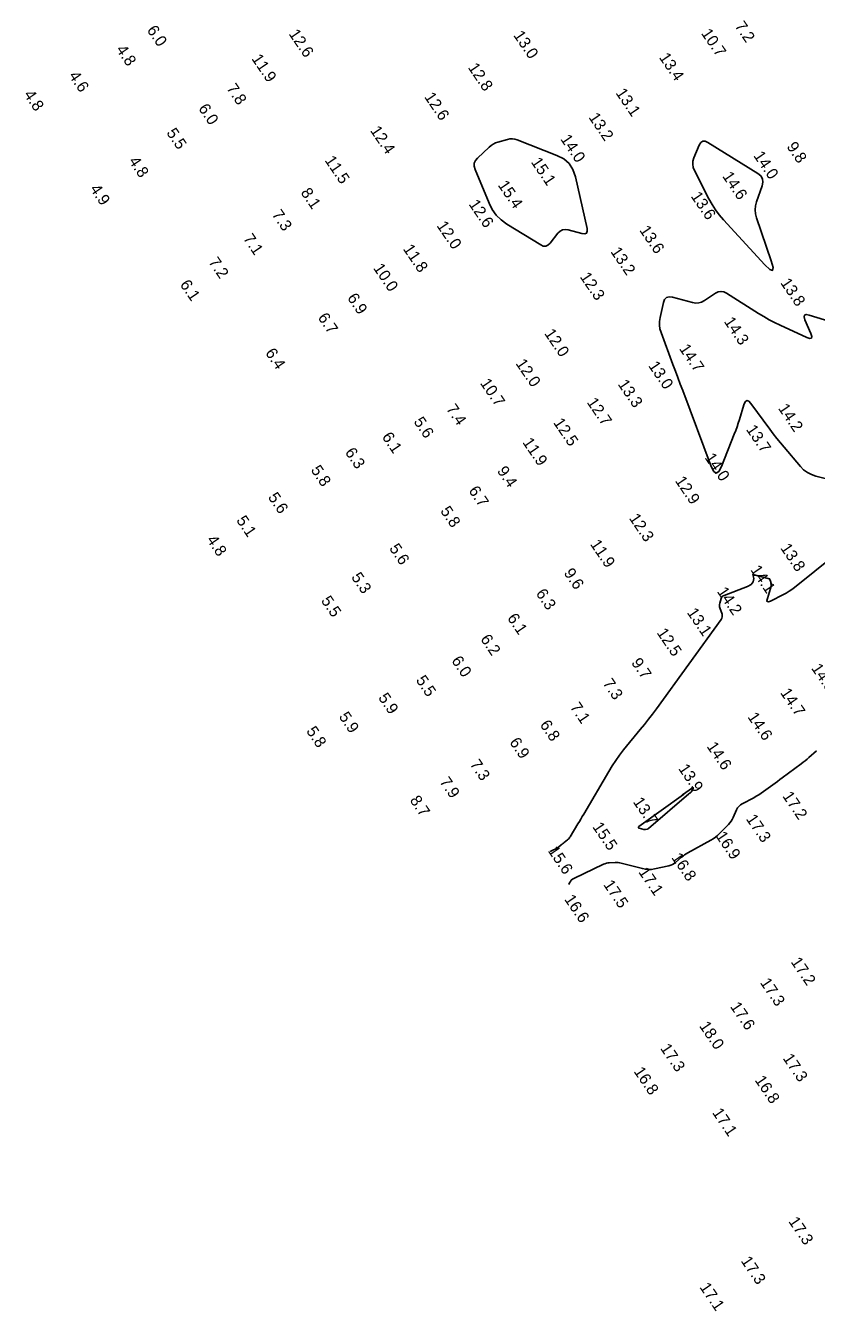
# Model space of a CAD drawing. Extents: x 824616 to 827440, y 158441 to 163197.
# Drawn here: x 826004 to 826349, y 160339 to 160899 of the extents above; entities that cross this region are included whole.
import ezdxf

# ---------------------------------------------------------------- set-up
doc = ezdxf.new("R2010")
doc.units = 0
for name, color, linetype in [('V-CHAN-CONT-EL14', 7, 'Continuous'), ('V-CHAN-CONT-EL16', 7, 'Continuous'), ('V-TOPO-SOUN', 7, 'Continuous')]:
    doc.layers.add(name, color=color, linetype=linetype)

msp = doc.modelspace()

# ---------------------------------------------------------------- linework, layer by layer
at = {"layer": 'V-CHAN-CONT-EL14'}
for points in [[(826199.82, 160838.98), (826199.77, 160837.69), (826200.14, 160836.32), (826206.22, 160821.63), (826207.62, 160818.86), (826209.38, 160816.42), (826211.52, 160814.28), (826214.02, 160812.47), (826228.72, 160803.41), (826229.87, 160802.91), (826230.93, 160802.86), (826231.91, 160803.27), (826232.81, 160804.14), (826236.23, 160808.52), (826237.15, 160809.44), (826238.19, 160809.99), (826239.35, 160810.18), (826240.64, 160810.01), (826246.68, 160808.42), (826247.91, 160808.27), (826248.7, 160808.58), (826249.04, 160809.36), (826248.93, 160810.59), (826243.82, 160833.12), (826242.75, 160836.24), (826241.06, 160838.83), (826238.75, 160840.89), (826235.82, 160842.42), (826218.47, 160849.19), (826217.44, 160849.5), (826216.4, 160849.64), (826215.35, 160849.6), (826214.3, 160849.38), (826210.06, 160848.17), (826209.03, 160847.81), (826208.07, 160847.33), (826207.17, 160846.75), (826206.33, 160846.05), (826201.21, 160841.26), (826200.3, 160840.16)], [(826294.94, 160838.54), (826295.15, 160837.18), (826295.68, 160835.83), (826301.98, 160823.52), (826303.34, 160821.08), (826304.85, 160818.74), (826306.52, 160816.51), (826308.34, 160814.39), (826326.38, 160794.79), (826328.54, 160792.73), (826329.72, 160792.32), (826329.93, 160793.55), (826329.15, 160796.44), (826322.76, 160815.2), (826322.31, 160816.94), (826322.17, 160818.68), (826322.32, 160820.43), (826322.78, 160822.17), (826325.18, 160829.14), (826325.52, 160830.78), (826325.31, 160832.24), (826324.55, 160833.5), (826323.26, 160834.57), (826301.54, 160848.08), (826300.34, 160848.61), (826299.32, 160848.58), (826298.47, 160848.01), (826297.8, 160846.89), (826295.47, 160841.31), (826295.05, 160839.92)], [(826290.31, 160563.83), (826290.34, 160563.86), (826290.43, 160563.92), (826294.85, 160566.93), (826295.04, 160567.03), (826295.14, 160567.03), (826295.15, 160566.93), (826295.08, 160566.73), (826294.45, 160565.33), (826294.42, 160565.28), (826294.39, 160565.23), (826294.35, 160565.19), (826294.32, 160565.14), (826294.15, 160564.98), (826294.11, 160564.94), (826294.07, 160564.9), (826294.02, 160564.87), (826293.97, 160564.84), (826293.59, 160564.62), (826293.51, 160564.58), (826293.43, 160564.53), (826293.36, 160564.47), (826293.29, 160564.41), (826275.68, 160549.28), (826275.54, 160549.18), (826275.39, 160549.09), (826275.23, 160549.02), (826275.06, 160548.98), (826274.37, 160548.83), (826274.2, 160548.8), (826274.03, 160548.79), (826273.86, 160548.8), (826273.69, 160548.84), (826271.64, 160549.38), (826271.33, 160549.5), (826271.21, 160549.65), (826271.27, 160549.84), (826271.51, 160550.07), (826290.96, 160564.12), (826291.05, 160564.18), (826291.07, 160564.21), (826291.04, 160564.2), (826290.94, 160564.15), (826290.44, 160563.89), (826290.35, 160563.84)]]:
    msp.add_lwpolyline(points, close=True, dxfattribs=at)
for points in [[(826358.34, 160700.18), (826348.54, 160702.77), (826346.61, 160703.43), (826344.85, 160704.35), (826343.25, 160705.53), (826341.82, 160706.98), (826334.71, 160715.28), (826333.1, 160717.2), (826331.52, 160719.16), (826329.97, 160721.14), (826328.47, 160723.15), (826320.23, 160734.36), (826319.3, 160735.35), (826318.49, 160735.59), (826317.8, 160735.09), (826317.25, 160733.84), (826315.29, 160727.37), (826314.78, 160725.76), (826314.24, 160724.16), (826313.66, 160722.57), (826313.05, 160721), (826307.43, 160706.88), (826306.29, 160704.73), (826305.17, 160704.02), (826304.06, 160704.75), (826302.96, 160706.93), (826290.56, 160739.94), (826289.49, 160742.79), (826288.43, 160745.64), (826287.37, 160748.49), (826286.31, 160751.35), (826281.13, 160765.34), (826280.67, 160766.92), (826280.44, 160768.51), (826280.46, 160770.12), (826280.71, 160771.74), (826282.18, 160778.28), (826282.7, 160779.65), (826283.54, 160780.51), (826284.69, 160780.85), (826286.15, 160780.68), (826294.87, 160778.33), (826296.24, 160778.11), (826297.56, 160778.17), (826298.83, 160778.53), (826300.05, 160779.17), (826304.85, 160782.33), (826306.06, 160782.93), (826307.26, 160783.14), (826308.47, 160782.95), (826309.69, 160782.38), (826323.62, 160773.56), (826325.91, 160772.17), (826328.24, 160770.85), (826330.61, 160769.62), (826333.03, 160768.46), (826344.67, 160763.12), (826345.9, 160762.71), (826346.59, 160762.85), (826346.75, 160763.54), (826346.38, 160764.78), (826343.83, 160770.83), (826343.47, 160772.1), (826343.66, 160772.86), (826344.4, 160773.12), (826345.7, 160772.89), (826366.09, 160766.58)], [(826392.42, 160696.85), (826339.2, 160654.22), (826338.06, 160653.36), (826336.88, 160652.56), (826335.66, 160651.82), (826334.4, 160651.15), (826328.77, 160648.31), (826327.92, 160647.99), (826327.41, 160648.08), (826327.25, 160648.57), (826327.43, 160649.45), (826328.82, 160653.8), (826329.06, 160654.87), (826329.08, 160655.93), (826328.87, 160656.96), (826328.44, 160657.97), (826321.09, 160659.9), (826321.49, 160658.17), (826321.24, 160656.74), (826320.34, 160655.59), (826318.8, 160654.72), (826308.6, 160650.77), (826308.15, 160650.54), (826307.79, 160650.23), (826307.51, 160649.84), (826307.31, 160649.37), (826306.71, 160647.34), (826306.59, 160646.83), (826306.56, 160646.33), (826306.62, 160645.83), (826306.75, 160645.32), (826307.69, 160642.63), (826307.82, 160642.02), (826307.81, 160641.44), (826307.65, 160640.88), (826307.35, 160640.34), (826279.1, 160601.41), (826277.4, 160599.11), (826275.67, 160596.83), (826273.91, 160594.57), (826272.11, 160592.35), (826264.86, 160583.48), (826263.09, 160581.23), (826261.41, 160578.92), (826259.83, 160576.54), (826258.34, 160574.1), (826247.49, 160555.49), (826246.86, 160554.43), (826246.23, 160553.36), (826245.6, 160552.3), (826244.96, 160551.23), (826241.58, 160545.64), (826241.33, 160545.27), (826241.06, 160544.93), (826240.75, 160544.61), (826240.41, 160544.33), (826238.92, 160543.15), (826238.61, 160542.91), (826238.31, 160542.67), (826238.01, 160542.43), (826237.71, 160542.19), (826236.43, 160541.18), (826236.16, 160540.97), (826235.88, 160540.77), (826235.58, 160540.59), (826235.28, 160540.43), (826234.06, 160539.79), (826233.75, 160539.63), (826233.44, 160539.48), (826233.12, 160539.34), (826232.91, 160539.25)]]:
    msp.add_lwpolyline(points, dxfattribs=at)
at = {"layer": 'V-CHAN-CONT-EL16'}
msp.add_lwpolyline([(826241.05, 160524.92), (826241.32, 160525.58), (826241.64, 160526.2), (826242.06, 160526.74), (826242.57, 160527.18), (826243.18, 160527.54), (826256.14, 160533.67), (826256.73, 160533.92), (826257.34, 160534.11), (826257.97, 160534.24), (826258.61, 160534.3), (826261.2, 160534.46), (826261.84, 160534.47), (826262.48, 160534.43), (826263.12, 160534.34), (826263.75, 160534.2), (826273.01, 160531.77), (826274.32, 160531.5), (826275.64, 160531.4), (826276.95, 160531.45), (826278.27, 160531.66), (826284.55, 160533.04), (826285.35, 160533.27), (826286.11, 160533.59), (826286.82, 160534.01), (826287.49, 160534.51), (826290.06, 160536.73), (826290.72, 160537.26), (826291.4, 160537.76), (826292.11, 160538.22), (826292.84, 160538.65), (826302.78, 160544.15), (826303.82, 160544.78), (826304.81, 160545.47), (826305.75, 160546.24), (826306.63, 160547.08), (826310.45, 160551.01), (826311.07, 160551.69), (826311.62, 160552.43), (826312.1, 160553.21), (826312.52, 160554.03), (826314.05, 160557.42), (826314.49, 160558.21), (826315.03, 160558.91), (826315.69, 160559.5), (826316.46, 160559.99), (826321.48, 160562.67), (826322.58, 160563.28), (826323.66, 160563.93), (826324.72, 160564.61), (826325.75, 160565.33), (826329.86, 160568.3), (826330.89, 160569.04), (826331.91, 160569.79), (826332.93, 160570.54), (826333.94, 160571.29), (826342.22, 160577.45), (826343.06, 160578.09), (826343.9, 160578.75), (826344.71, 160579.43), (826345.52, 160580.13), (826348.77, 160583.02)], dxfattribs=at)

# ---------------------------------------------------------------- texts
at = {"layer": 'V-TOPO-SOUN'}
for s, p in [('7.2', (826313.04, 160898.76)), ('6.0', (826057.04, 160896.98)), ('12.6 ', (826118.82, 160895.34)), ('13.0 ', (826216.65, 160894.72)), ('10.7 ', (826298.41, 160895.59)), ('4.8', (826043.62, 160888.5)), ('11.9 ', (826102.62, 160884.52)), ('13.4 ', (826280.08, 160885.08)), ('12.8 ', (826196.86, 160880.67)), ('4.6', (826023, 160877.11)), ('7.8', (826091.7, 160871.6)), ('4.8', (826003.44, 160868.88)), ('12.6 ', (826177.85, 160867.9)), ('13.1 ', (826261.18, 160869.62)), ('6.0', (826079.46, 160862.84)), ('13.2 ', (826249.4, 160858.98)), ('5.5', (826065.56, 160852.22)), ('12.4 ', (826154.27, 160853.23)), ('14.0 ', (826237.11, 160849.53)), ('9.8', (826335.65, 160846.23)), ('4.8', (826049.1, 160839.92)), ('11.5 ', (826134.47, 160840.26)), ('15.1 ', (826224.3, 160839.52)), ('14.0 ', (826321.21, 160842.26)), ('14.6 ', (826307.65, 160833.33)), ('4.9', (826032.23, 160827.83)), ('8.1', (826124.03, 160826.21)), ('15.4 ', (826209.88, 160829.47)), ('12.6 ', (826197.19, 160821.15)), ('13.6 ', (826293.92, 160824.6)), ('7.3', (826111.45, 160816.68)), ('12.0 ', (826183.23, 160811.8)), ('13.6 ', (826271.51, 160809.84)), ('7.1', (826098.95, 160806.21)), ('11.8 ', (826168.58, 160801.69)), ('13.2 ', (826258.95, 160800.48)), ('7.2', (826083.88, 160795.98)), ('10.0 ', (826155.6, 160793.34)), ('12.3 ', (826245.61, 160789.52)), ('6.1', (826071.44, 160786.18)), ('13.8 ', (826332.92, 160786.92)), ('6.9', (826144.27, 160780.33)), ('6.7', (826131.47, 160771.77)), ('12.0 ', (826230.11, 160764.89)), ('14.3 ', (826308.34, 160770.06)), ('6.4', (826108.59, 160756.39)), ('14.7 ', (826288.83, 160758.25)), ('12.0 ', (826217.64, 160751.78)), ('13.0 ', (826275.41, 160750.8)), ('10.7 ', (826202.14, 160743.24)), ('13.3 ', (826262.12, 160742.79)), ('7.4', (826187.4, 160732.02)), ('12.7 ', (826248.63, 160734.87)), ('14.2 ', (826331.94, 160732.26)), ('5.6', (826173.22, 160726.43)), ('12.5 ', (826234.03, 160726.02)), ('6.1', (826159.4, 160719.83)), ('13.7 ', (826317.98, 160723.06)), ('11.9 ', (826220.62, 160717.44)), ('6.3', (826143.29, 160713.08)), ('14.0 ', (826299.96, 160710.77)), ('5.8', (826128.42, 160705.39)), ('9.4', (826209.53, 160704.99)), ('12.9 ', (826287.03, 160700.7)), ('5.6', (826109.78, 160693.55)), ('6.7', (826197.13, 160696.39)), ('5.8', (826184.84, 160687.55)), ('5.1', (826095.98, 160683.43)), ('12.3 ', (826267.01, 160684.41)), ('4.8', (826083.06, 160675)), ('5.6', (826162.58, 160671.25)), ('11.9 ', (826250.07, 160673.1)), ('13.8 ', (826332.91, 160671.42)), ('5.3', (826146.03, 160658.72)), ('9.6', (826238.58, 160660.54)), ('14.1 ', (826319.89, 160661.94)), ('5.5', (826132.89, 160648.49)), ('6.3', (826226.43, 160651.63)), ('14.2 ', (826305.34, 160652.44)), ('13.1 ', (826292.23, 160643.3)), ('6.1', (826213.96, 160640.92)), ('6.2', (826202.28, 160631.78)), ('12.5 ', (826279.08, 160634.51)), ('6.0', (826189.67, 160622.35)), ('9.7', (826267.99, 160621.46)), ('14.5 ', (826346.37, 160619.07)), ('5.5', (826174.17, 160613.88)), ('7.3', (826255.56, 160612.51)), ('14.7 ', (826332.86, 160608.39)), ('5.9', (826157.79, 160606.22)), ('7.1', (826241.33, 160602.14)), ('5.9', (826140.63, 160597.98)), ('14.6 ', (826318.62, 160597.85)), ('5.8', (826126.45, 160591.69)), ('6.8', (826228.19, 160594.45)), ('6.9', (826214.94, 160586.82)), ('14.6 ', (826300.84, 160585)), ('7.3', (826197.71, 160577.28)), ('13.9 ', (826288.47, 160575.35)), ('7.9', (826184.51, 160569.63)), ('17.2 ', (826333.81, 160563.41)), ('8.7', (826171.53, 160561.57)), ('13.7 ', (826268.72, 160560.88)), ('17.3 ', (826317.96, 160553.44)), ('15.5 ', (826251.07, 160550)), ('16.9 ', (826304.74, 160546.01)), ('15.6 ', (826231.67, 160539.57)), ('16.8 ', (826285.46, 160536.63)), ('17.1 ', (826271.1, 160530.32)), ('17.5 ', (826255.83, 160524.83)), ('16.6 ', (826238.81, 160518.46)), ('17.2 ', (826337.46, 160491.18)), ('17.3 ', (826324.06, 160482.15)), ('17.6 ', (826311.04, 160471.72)), ('18.0 ', (826297.57, 160463.26)), ('17.3 ', (826280.59, 160453.56)), ('17.3 ', (826333.99, 160449.2)), ('16.8 ', (826269.06, 160443.46)), ('16.8 ', (826321.76, 160439.68)), ('17.1 ', (826303.24, 160425.52)), ('17.3 ', (826336.41, 160378.17)), ('17.3 ', (826315.72, 160360.96)), ('17.1 ', (826297.74, 160349.5))]:
    msp.add_text(s, height=5, rotation=304.2, dxfattribs=at).set_placement(p)

doc.saveas('drawing.dxf')
